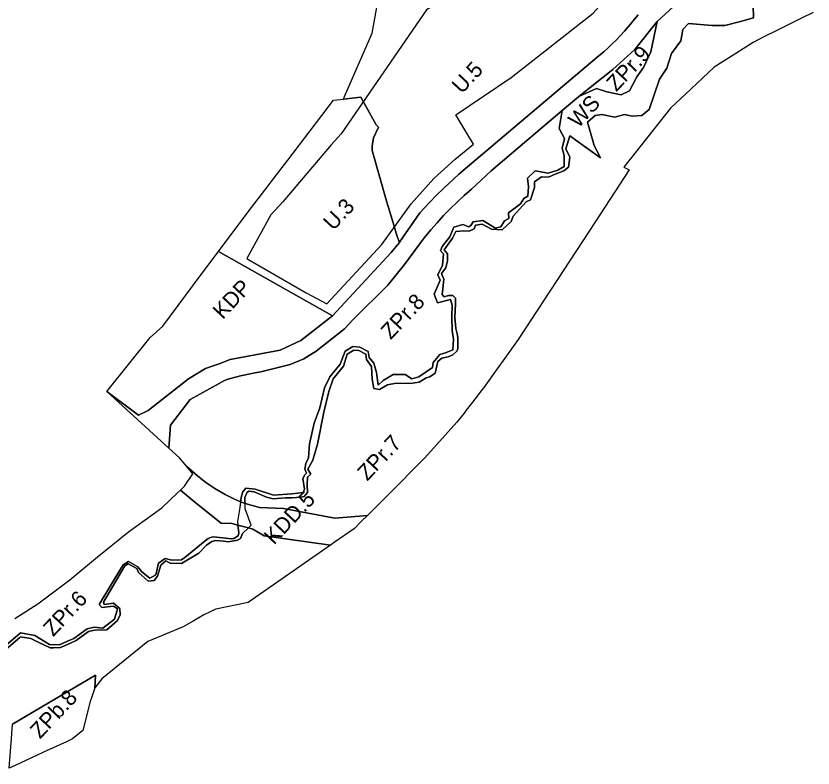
# Model space of a CAD drawing. Extents: x 7425782 to 7428854, y 5550411 to 5553074.
# Drawn here: x 7426859.1 to 7427315.3, y 5551271.3 to 5551702 of the extents above; entities that cross this region are included whole.
import ezdxf

# ---------------------------------------------------------------- set-up
doc = ezdxf.new("R2010")
doc.units = 0
for name, color, linetype in [('LIN_Linie rozgraniczajace WS', 7, 'Continuous'), ('LIN_linie_rozgraniczajace', 7, 'Continuous'), ('LIN_nieprzekraczalna linia zabudowy', 7, 'Continuous'), ('TXT_oznaczenia przeznaczen', 7, 'Continuous')]:
    doc.layers.add(name, color=color, linetype=linetype)

msp = doc.modelspace()

# ---------------------------------------------------------------- linework, layer by layer
at = {"layer": 'LIN_Linie rozgraniczajace WS'}
for points in [[(7426987.63, 5551423.77), (7426987.13, 5551420.51), (7426985.88, 5551412.53), (7426986.15, 5551410.37)], [(7426992.14, 5551408.81), (7426993.77, 5551410.36), (7426990.26, 5551419.81), (7426990.19, 5551422.72)]]:
    msp.add_lwpolyline(points, dxfattribs=at)
at = {"layer": 'LIN_linie_rozgraniczajace'}
for points in [[(7427215.26, 5551702.62), (7427212.2, 5551698.98), (7427211.72, 5551698.4), (7427209.57, 5551695.83), (7427207.36, 5551693.31), (7427205.08, 5551690.85), (7427202.76, 5551688.43), (7427200.38, 5551686.07), (7427197.94, 5551683.76), (7427195.46, 5551681.51), (7427192.92, 5551679.31), (7427112.56, 5551611.38), (7427103.79, 5551603.22), (7427099.74, 5551599.29), (7427095.81, 5551595.24), (7427090.26, 5551589.21), (7427078.65, 5551572.44), (7427078.53, 5551572.29), (7427077.23, 5551575.79), (7427074.41, 5551585.38), (7427071.29, 5551595.45), (7427062.98, 5551625.05), (7427063.01, 5551627.44), (7427063.81, 5551632.16), (7427066.54, 5551638.39), (7427065.17, 5551639.71), (7427056.47, 5551655.47), (7427046.51, 5551654.42), (7427047.03, 5551655.97), (7427062.95, 5551692.14), (7427066.49, 5551712.37)], [(7427240.05, 5551711.78), (7427226.11, 5551698.89), (7427213.3, 5551682.79), (7427200.78, 5551671.27), (7427181.31, 5551655.85), (7427171.71, 5551647.91), (7427131.08, 5551613.29), (7427119.82, 5551602.79), (7427115.67, 5551599.17), (7427111.61, 5551595.44), (7427107.67, 5551591.6), (7427103.83, 5551587.66), (7427100.1, 5551583.6), (7427096.49, 5551579.45), (7427092.99, 5551575.19), (7427089.97, 5551571.31), (7427081.48, 5551559.65), (7427071.96, 5551547.87), (7427052.36, 5551528.36), (7427047.04, 5551522.85), (7427030.93, 5551510.01), (7427023.9, 5551505.66), (7427015.96, 5551502.31), (7427000.07, 5551498.33), (7426995.12, 5551497.42), (7426987.59, 5551495.95), (7426979.81, 5551493.76), (7426977.97, 5551493), (7426975.37, 5551491.43), (7426958.84, 5551482.32), (7426947.59, 5551467.59), (7426946.66, 5551454.53), (7426911.05, 5551487.01), (7426929.18, 5551473.42), (7426934.76, 5551476.14), (7426957.8, 5551494.22), (7426967.61, 5551500.12), (7426972.44, 5551501.86), (7426975.4, 5551502.85), (7426981.69, 5551505.17), (7427010.32, 5551510.52), (7427022.17, 5551516.16), (7427040.25, 5551530.24), (7427073.8, 5551566.57), (7427078.53, 5551572.29), (7427078.65, 5551572.44), (7427090.26, 5551589.21), (7427095.81, 5551595.24), (7427099.74, 5551599.29), (7427103.79, 5551603.22), (7427112.56, 5551611.38), (7427192.92, 5551679.31), (7427195.46, 5551681.51), (7427197.94, 5551683.76), (7427200.38, 5551686.07), (7427202.76, 5551688.43), (7427205.08, 5551690.85), (7427207.36, 5551693.31), (7427209.57, 5551695.83), (7427211.72, 5551698.4), (7427212.2, 5551698.98), (7427215.26, 5551702.62)], [(7427281.08, 5551708.22), (7427281.22, 5551700.92), (7427273.77, 5551698.78), (7427264.87, 5551696.48), (7427257.57, 5551696.47), (7427243.93, 5551697.6), (7427240.78, 5551694.21), (7427239.69, 5551687.75), (7427234.21, 5551680.55), (7427231.68, 5551672.18), (7427227.37, 5551665.82), (7427221.44, 5551648.35), (7427217.28, 5551645.06), (7427211.77, 5551644.6), (7427207.42, 5551645.49), (7427201.92, 5551644.04), (7427194.4, 5551645.55), (7427190.6, 5551645.05), (7427186.22, 5551641.16), (7427190.06, 5551627.77), (7427193.66, 5551620.75), (7427185.56, 5551626.47), (7427176.02, 5551633.45), (7427173.77, 5551625.86), (7427176.01, 5551621.2), (7427175.37, 5551615.37), (7427172.73, 5551613.34), (7427167.75, 5551611.38), (7427163.95, 5551609.64), (7427159.95, 5551609.83), (7427155.91, 5551606.94), (7427155.96, 5551603.75), (7427153.61, 5551596.74), (7427151.1, 5551595.51), (7427143.6, 5551587.42), (7427142.52, 5551584.39), (7427137.34, 5551579.46), (7427131.26, 5551579.9), (7427125.93, 5551582.86), (7427122.07, 5551582.23), (7427121.32, 5551580.06), (7427118.57, 5551578.84), (7427115.4, 5551579.02), (7427110.83, 5551578.55), (7427108.96, 5551574.68), (7427104.25, 5551568.07), (7427106.16, 5551565.69), (7427106.1, 5551561.83), (7427105.19, 5551557.67), (7427102.64, 5551554.49), (7427103.99, 5551551.21), (7427103.49, 5551545.69), (7427102.96, 5551542.49), (7427104.14, 5551541.21), (7427106.67, 5551541.97), (7427109.16, 5551541.89), (7427110.69, 5551540.38), (7427110.74, 5551537.16), (7427110.29, 5551529.39), (7427110.89, 5551523.07), (7427111.63, 5551520.05), (7427111.92, 5551517.82), (7427112.01, 5551511.54), (7427111.58, 5551510.2), (7427109.21, 5551507.86), (7427106.37, 5551506.83), (7427102.75, 5551505.99), (7427100.59, 5551504.15), (7427098.99, 5551497.53), (7427095.92, 5551495.28), (7427093.9, 5551494.73), (7427089.89, 5551492.27), (7427084.88, 5551491.47), (7427076.69, 5551491.8), (7427071.64, 5551490.77), (7427067.13, 5551488), (7427064, 5551488.56), (7427062.89, 5551493.97), (7427062.5, 5551501.26), (7427059.62, 5551505.21), (7427059.32, 5551508.3), (7427055.26, 5551510.5), (7427052.47, 5551510.64), (7427048.64, 5551508.41), (7427046.55, 5551501.45), (7427040.6, 5551494.22), (7427038.22, 5551486.86), (7427035.31, 5551475.07), (7427031.75, 5551456.79), (7427028.92, 5551447.59), (7427026.22, 5551442.49), (7427027.85, 5551439.5), (7427025.86, 5551437.94), (7427025.83, 5551433.52), (7427025.85, 5551429.01), (7427024, 5551426.8), (7427022.12, 5551426.49), (7427017.19, 5551426.09), (7427013.32, 5551426.01), (7427006.26, 5551425.5), (7427002.41, 5551426.44), (7426995.39, 5551429.47), (7426992.31, 5551429.78), (7426991.33, 5551429.27), (7426990.09, 5551426.25), (7426990.14, 5551424.38), (7426990.19, 5551422.72), (7426987.63, 5551423.77), (7426988.14, 5551427.03), (7426988.84, 5551429.54), (7426990.68, 5551431.55), (7426995.97, 5551431.06), (7427006.46, 5551427.54), (7427016.99, 5551428.29), (7427023.37, 5551429.09), (7427024.14, 5551431.01), (7427023.26, 5551437.08), (7427024.37, 5551439.21), (7427025.34, 5551440.2), (7427024.4, 5551442.45), (7427024.99, 5551445.75), (7427026.45, 5551449.03), (7427027.12, 5551456.99), (7427029.76, 5551468.86), (7427033.06, 5551477.52), (7427035.71, 5551489.12), (7427038.81, 5551495.42), (7427044.62, 5551502.67), (7427047.54, 5551510.07), (7427051.95, 5551512.71), (7427055.81, 5551512.24), (7427060.69, 5551509.84), (7427061.28, 5551506.36), (7427063.95, 5551503.12), (7427065.47, 5551497.77), (7427066.34, 5551490.59), (7427069.25, 5551493.31), (7427075, 5551496.66), (7427081.92, 5551496.6), (7427085.65, 5551494.28), (7427089.74, 5551495.24), (7427097.54, 5551500.6), (7427097.94, 5551503.48), (7427101.71, 5551508.22), (7427104.99, 5551509.06), (7427109.21, 5551510.73), (7427109.56, 5551516.93), (7427108.79, 5551521.92), (7427108.56, 5551529.7), (7427108.73, 5551536.46), (7427107.77, 5551539.69), (7427100.39, 5551537.74), (7427098.38, 5551542.62), (7427101.89, 5551550.69), (7427100.45, 5551553.73), (7427103.12, 5551559.27), (7427103.81, 5551565.82), (7427102.05, 5551567.56), (7427102.96, 5551569.97), (7427107.48, 5551575.45), (7427109.73, 5551581.06), (7427114.81, 5551582.57), (7427118.34, 5551581.16), (7427119.5, 5551581.99), (7427120.8, 5551584.18), (7427126.38, 5551584.81), (7427133.57, 5551580.45), (7427136.57, 5551581.19), (7427138.66, 5551584.76), (7427141.24, 5551585.99), (7427141.05, 5551589.29), (7427147.79, 5551594.5), (7427149.85, 5551597.56), (7427152.01, 5551598.74), (7427152.43, 5551604.43), (7427151.78, 5551609.06), (7427156.21, 5551613.35), (7427163.75, 5551612.04), (7427169.29, 5551613.77), (7427172.83, 5551615.88), (7427172.84, 5551622.01), (7427171.77, 5551626.27), (7427173.05, 5551631.91), (7427170.07, 5551637.59), (7427171.71, 5551647.91), (7427181.31, 5551655.85), (7427191.28, 5551660.53), (7427197.34, 5551658.49), (7427205.41, 5551656.8), (7427210.2, 5551659.15), (7427214.35, 5551667.11), (7427218.31, 5551672.58), (7427222.37, 5551681.5), (7427226.11, 5551698.89), (7427240.05, 5551711.78)], [(7427315.31, 5551703.95), (7427308.73, 5551700.68), (7427294.23, 5551693.48), (7427287.53, 5551690.16), (7427280.94, 5551686.89), (7427271.15, 5551680.59), (7427258.71, 5551672.59), (7427245.44, 5551660.18), (7427233.77, 5551649.26), (7427207.05, 5551615.38), (7427207.05, 5551615.38), (7427209.69, 5551614.03), (7427210.14, 5551613.8), (7427190.78, 5551584.27), (7427146.54, 5551516.77), (7427126.82, 5551489.17), (7427126.66, 5551488.96), (7427123.99, 5551485.52), (7427122.44, 5551483.51), (7427116.85, 5551476.28), (7427115.52, 5551474.56), (7427111.46, 5551469.31), (7427093.09, 5551448.86), (7427071.71, 5551427.46), (7427060.25, 5551415.99), (7427060.25, 5551415.99), (7427041.59, 5551414.41), (7427012.28, 5551419.87), (7426998.38, 5551420.46), (7426990.19, 5551422.72), (7426990.14, 5551424.38), (7426990.09, 5551426.25), (7426991.33, 5551429.27), (7426992.31, 5551429.78), (7426995.39, 5551429.47), (7427002.41, 5551426.44), (7427006.26, 5551425.5), (7427013.32, 5551426.01), (7427017.19, 5551426.09), (7427022.12, 5551426.49), (7427024, 5551426.8), (7427025.85, 5551429.01), (7427025.83, 5551433.52), (7427025.86, 5551437.94), (7427027.85, 5551439.5), (7427026.22, 5551442.49), (7427028.92, 5551447.59), (7427031.75, 5551456.79), (7427035.31, 5551475.07), (7427038.22, 5551486.86), (7427040.6, 5551494.22), (7427046.55, 5551501.45), (7427048.64, 5551508.41), (7427052.47, 5551510.64), (7427055.26, 5551510.5), (7427059.32, 5551508.3), (7427059.62, 5551505.21), (7427062.5, 5551501.26), (7427062.89, 5551493.97), (7427064, 5551488.56), (7427067.13, 5551488), (7427071.64, 5551490.77), (7427076.69, 5551491.8), (7427084.88, 5551491.47), (7427089.89, 5551492.27), (7427093.9, 5551494.73), (7427095.92, 5551495.28), (7427098.99, 5551497.53), (7427100.59, 5551504.15), (7427102.75, 5551505.99), (7427106.37, 5551506.83), (7427109.21, 5551507.86), (7427111.58, 5551510.2), (7427112.01, 5551511.54), (7427111.92, 5551517.82), (7427111.63, 5551520.05), (7427110.89, 5551523.07), (7427110.29, 5551529.39), (7427110.74, 5551537.16), (7427110.69, 5551540.38), (7427109.16, 5551541.89), (7427106.67, 5551541.97), (7427104.14, 5551541.21), (7427102.96, 5551542.49), (7427103.49, 5551545.69), (7427103.99, 5551551.21), (7427102.64, 5551554.49), (7427105.19, 5551557.67), (7427106.1, 5551561.83), (7427106.16, 5551565.69), (7427104.25, 5551568.07), (7427108.96, 5551574.68), (7427110.83, 5551578.55), (7427115.4, 5551579.02), (7427118.57, 5551578.84), (7427121.32, 5551580.06), (7427122.07, 5551582.23), (7427125.93, 5551582.86), (7427131.26, 5551579.9), (7427137.34, 5551579.46), (7427142.52, 5551584.39), (7427143.6, 5551587.42), (7427151.1, 5551595.51), (7427153.61, 5551596.74), (7427155.96, 5551603.75), (7427155.91, 5551606.94), (7427159.95, 5551609.83), (7427163.95, 5551609.64), (7427167.75, 5551611.38), (7427172.73, 5551613.34), (7427175.37, 5551615.37), (7427176.01, 5551621.2), (7427173.77, 5551625.86), (7427176.02, 5551633.45), (7427185.56, 5551626.47), (7427193.66, 5551620.75), (7427190.06, 5551627.77), (7427186.22, 5551641.16), (7427190.6, 5551645.05), (7427194.4, 5551645.55), (7427201.92, 5551644.04), (7427207.42, 5551645.49), (7427211.77, 5551644.6), (7427217.28, 5551645.06), (7427221.44, 5551648.35), (7427227.37, 5551665.82), (7427231.68, 5551672.18), (7427234.21, 5551680.55), (7427239.69, 5551687.75), (7427240.78, 5551694.21), (7427243.93, 5551697.6), (7427257.57, 5551696.47), (7427264.87, 5551696.48), (7427273.77, 5551698.78), (7427281.22, 5551700.92), (7427281.08, 5551708.22)], [(7426858.52, 5551356.89), (7426871.59, 5551365.28), (7426889.82, 5551378.99), (7426904.52, 5551391.21), (7426923.5, 5551406.59), (7426942.59, 5551420.23), (7426951.55, 5551428.85), (7426953.18, 5551430.37), (7426961.54, 5551423.51), (7426976.56, 5551411.51), (7426982.65, 5551411.28), (7426986.15, 5551410.37), (7426986.71, 5551405.97), (7426986.31, 5551404.35), (7426983.7, 5551402.69), (7426982.44, 5551402.57), (7426972.12, 5551403.64), (7426971.06, 5551403.45), (7426969.11, 5551402.82), (7426967.43, 5551401.37), (7426955.66, 5551391.86), (7426953.9, 5551390.58), (7426948.21, 5551390.29), (7426944.55, 5551391.37), (7426940.74, 5551388.66), (7426939.16, 5551381.96), (7426935.62, 5551379.99), (7426931.04, 5551383.72), (7426928.85, 5551386.59), (7426923.4, 5551389.48), (7426920.44, 5551387.65), (7426919.56, 5551386.16), (7426906.64, 5551364.96), (7426908.28, 5551363.28), (7426914.83, 5551364.05), (7426917.21, 5551362.39), (7426915.54, 5551356.48), (7426908.72, 5551351.42), (7426903.8, 5551351.98), (7426899.87, 5551351.08), (7426892.17, 5551345.44), (7426883.71, 5551341.77), (7426878.32, 5551341.99), (7426869.91, 5551347.17), (7426861.62, 5551348.67), (7426839.69, 5551329.93)], [(7426839.69, 5551329.93), (7426861.62, 5551348.67), (7426869.91, 5551347.17), (7426878.32, 5551341.99), (7426883.71, 5551341.77), (7426892.17, 5551345.44), (7426899.87, 5551351.08), (7426903.8, 5551351.98), (7426908.72, 5551351.42), (7426915.54, 5551356.48), (7426917.21, 5551362.39), (7426914.83, 5551364.05), (7426908.28, 5551363.28), (7426906.64, 5551364.96), (7426919.56, 5551386.16), (7426920.44, 5551387.65), (7426923.4, 5551389.48), (7426928.85, 5551386.59), (7426931.04, 5551383.72), (7426935.62, 5551379.99), (7426939.16, 5551381.96), (7426940.74, 5551388.66), (7426944.55, 5551391.37), (7426948.21, 5551390.29), (7426953.9, 5551390.58), (7426955.66, 5551391.86), (7426967.43, 5551401.37), (7426969.11, 5551402.82), (7426971.06, 5551403.45), (7426972.12, 5551403.64), (7426982.44, 5551402.57), (7426983.7, 5551402.69), (7426986.31, 5551404.35), (7426986.71, 5551405.97), (7426986.15, 5551410.37), (7426992.14, 5551408.81), (7426988.78, 5551405.6), (7426987.6, 5551402.71), (7426985.81, 5551401.7), (7426980.8, 5551400.93), (7426977.82, 5551401.14), (7426973.47, 5551401.51), (7426971.21, 5551401.11), (7426968.2, 5551398.89), (7426963.66, 5551394.3), (7426953.77, 5551388.36), (7426947.42, 5551388.58), (7426944.89, 5551389.9), (7426941.93, 5551387.49), (7426940.18, 5551381.08), (7426938.16, 5551378.6), (7426934.83, 5551378.32), (7426929.23, 5551383.31), (7426928.25, 5551385.5), (7426923.24, 5551388.26), (7426921.31, 5551387.15), (7426909.12, 5551366.22), (7426909.49, 5551364.86), (7426914.86, 5551365.74), (7426918.47, 5551362.67), (7426918.79, 5551358.97), (7426917.19, 5551355.87), (7426911.12, 5551350.42), (7426904.07, 5551350.24), (7426900.5, 5551349.44), (7426893.54, 5551344.38), (7426890.23, 5551342.85), (7426884.59, 5551340.26), (7426880.65, 5551340.14), (7426878.59, 5551340.08), (7426871.69, 5551343.44), (7426867.57, 5551345.45), (7426861.7, 5551346.44), (7426861.25, 5551346.13), (7426841.49, 5551329.22)], [(7426841.49, 5551329.22), (7426861.25, 5551346.13), (7426861.7, 5551346.44), (7426867.57, 5551345.45), (7426871.69, 5551343.44), (7426878.59, 5551340.08), (7426880.65, 5551340.14), (7426884.59, 5551340.26), (7426890.23, 5551342.85), (7426893.54, 5551344.38), (7426900.5, 5551349.44), (7426904.07, 5551350.24), (7426911.12, 5551350.42), (7426917.19, 5551355.87), (7426918.79, 5551358.97), (7426918.47, 5551362.67), (7426914.86, 5551365.74), (7426909.49, 5551364.86), (7426909.12, 5551366.22), (7426921.31, 5551387.15), (7426923.24, 5551388.26), (7426928.25, 5551385.5), (7426929.23, 5551383.31), (7426934.83, 5551378.32), (7426938.16, 5551378.6), (7426940.18, 5551381.08), (7426941.93, 5551387.49), (7426944.89, 5551389.9), (7426947.42, 5551388.58), (7426953.77, 5551388.36), (7426963.66, 5551394.3), (7426968.2, 5551398.89), (7426971.21, 5551401.11), (7426973.47, 5551401.51), (7426977.82, 5551401.14), (7426980.8, 5551400.93), (7426985.81, 5551401.7), (7426987.6, 5551402.71), (7426988.78, 5551405.6), (7426992.14, 5551408.81), (7426994.66, 5551408.16), (7427001.19, 5551404.33), (7427039.16, 5551398.99), (7427039.16, 5551398.99), (7426992.01, 5551366.07), (7426973.57, 5551362.21), (7426969.94, 5551360.49), (7426966.65, 5551358.94), (7426960.47, 5551355.41), (7426954.82, 5551352.18), (7426934.6, 5551343.67), (7426934.6, 5551343.67), (7426908.28, 5551322.32), (7426904.25, 5551317.27), (7426904.68, 5551324.5), (7426857.13, 5551296.4)]]:
    msp.add_lwpolyline(points, dxfattribs=at)
for points in [[(7427181.31, 5551655.85), (7427200.78, 5551671.27), (7427213.3, 5551682.79), (7427226.11, 5551698.89), (7427222.37, 5551681.5), (7427218.31, 5551672.58), (7427214.35, 5551667.11), (7427210.2, 5551659.15), (7427205.41, 5551656.8), (7427197.34, 5551658.49), (7427191.28, 5551660.53)], [(7427078.53, 5551572.29), (7427073.8, 5551566.57), (7427040.25, 5551530.24), (7426974.95, 5551567.07), (7426992, 5551589.77), (7427003.48, 5551604.79), (7427006.34, 5551608.53), (7427014.69, 5551619.47), (7427040.87, 5551653.76), (7427046.51, 5551654.42), (7427056.47, 5551655.47), (7427065.17, 5551639.71), (7427066.54, 5551638.39), (7427063.81, 5551632.16), (7427063.01, 5551627.44), (7427062.98, 5551625.05), (7427071.29, 5551595.45), (7427074.41, 5551585.38), (7427077.23, 5551575.79)], [(7426987.63, 5551423.77), (7426983.71, 5551425.45), (7426978.79, 5551427.92), (7426972.96, 5551431.32), (7426967.76, 5551434.86), (7426962.89, 5551438.66), (7426956.8, 5551444.07), (7426952.76, 5551448.96), (7426946.66, 5551454.53), (7426947.59, 5551467.59), (7426958.84, 5551482.32), (7426975.37, 5551491.43), (7426977.97, 5551493), (7426979.81, 5551493.76), (7426987.59, 5551495.95), (7426995.12, 5551497.42), (7427000.07, 5551498.33), (7427015.96, 5551502.31), (7427023.9, 5551505.66), (7427030.93, 5551510.01), (7427047.04, 5551522.85), (7427052.36, 5551528.36), (7427071.96, 5551547.87), (7427081.48, 5551559.65), (7427089.97, 5551571.31), (7427092.99, 5551575.19), (7427096.49, 5551579.45), (7427100.1, 5551583.6), (7427103.83, 5551587.66), (7427107.67, 5551591.6), (7427111.61, 5551595.44), (7427115.67, 5551599.17), (7427119.82, 5551602.79), (7427131.08, 5551613.29), (7427171.71, 5551647.91), (7427170.07, 5551637.59), (7427173.05, 5551631.91), (7427171.77, 5551626.27), (7427172.84, 5551622.01), (7427172.83, 5551615.88), (7427169.29, 5551613.77), (7427163.75, 5551612.04), (7427156.21, 5551613.35), (7427151.78, 5551609.06), (7427152.43, 5551604.43), (7427152.01, 5551598.74), (7427149.85, 5551597.56), (7427147.79, 5551594.5), (7427141.05, 5551589.29), (7427141.24, 5551585.99), (7427138.66, 5551584.76), (7427136.57, 5551581.19), (7427133.57, 5551580.45), (7427126.38, 5551584.81), (7427120.8, 5551584.18), (7427119.5, 5551581.99), (7427118.34, 5551581.16), (7427114.81, 5551582.57), (7427109.73, 5551581.06), (7427107.48, 5551575.45), (7427102.96, 5551569.97), (7427102.05, 5551567.56), (7427103.81, 5551565.82), (7427103.12, 5551559.27), (7427100.45, 5551553.73), (7427101.89, 5551550.69), (7427098.38, 5551542.62), (7427100.39, 5551537.74), (7427107.77, 5551539.69), (7427108.73, 5551536.46), (7427108.56, 5551529.7), (7427108.79, 5551521.92), (7427109.56, 5551516.93), (7427109.21, 5551510.73), (7427104.99, 5551509.06), (7427101.71, 5551508.22), (7427097.94, 5551503.48), (7427097.54, 5551500.6), (7427089.74, 5551495.24), (7427085.65, 5551494.28), (7427081.92, 5551496.6), (7427075, 5551496.66), (7427069.25, 5551493.31), (7427066.34, 5551490.59), (7427065.47, 5551497.77), (7427063.95, 5551503.12), (7427061.28, 5551506.36), (7427060.69, 5551509.84), (7427055.81, 5551512.24), (7427051.95, 5551512.71), (7427047.54, 5551510.07), (7427044.62, 5551502.67), (7427038.81, 5551495.42), (7427035.71, 5551489.12), (7427033.06, 5551477.52), (7427029.76, 5551468.86), (7427027.12, 5551456.99), (7427026.45, 5551449.03), (7427024.99, 5551445.75), (7427024.4, 5551442.45), (7427025.34, 5551440.2), (7427024.37, 5551439.21), (7427023.26, 5551437.08), (7427024.14, 5551431.01), (7427023.37, 5551429.09), (7427016.99, 5551428.29), (7427006.46, 5551427.54), (7426995.97, 5551431.06), (7426990.68, 5551431.55), (7426988.84, 5551429.54), (7426988.14, 5551427.03)], [(7427040.25, 5551530.24), (7427022.17, 5551516.16), (7427010.32, 5551510.52), (7426981.69, 5551505.17), (7426975.4, 5551502.85), (7426972.44, 5551501.86), (7426967.61, 5551500.12), (7426957.8, 5551494.22), (7426934.76, 5551476.14), (7426929.18, 5551473.42), (7426911.05, 5551487.01), (7426935.85, 5551517.88), (7426943.05, 5551524.29), (7426965.12, 5551554), (7426974.95, 5551567.07)], [(7427012.28, 5551419.87), (7427041.59, 5551414.41), (7427060.25, 5551415.99), (7427060.25, 5551415.99), (7427056.88, 5551412.61), (7427052.76, 5551408.48), (7427041.25, 5551400.45), (7427039.16, 5551398.99), (7427001.19, 5551404.33), (7426994.66, 5551408.16), (7426992.14, 5551408.81), (7426986.15, 5551410.37), (7426982.65, 5551411.28), (7426976.56, 5551411.51), (7426961.54, 5551423.51), (7426953.18, 5551430.37), (7426955.61, 5551432.63), (7426960.37, 5551439.75), (7426956.8, 5551444.07), (7426962.89, 5551438.66), (7426967.76, 5551434.86), (7426972.96, 5551431.32), (7426978.79, 5551427.92), (7426983.71, 5551425.45), (7426987.63, 5551423.77), (7426990.19, 5551422.72), (7426998.38, 5551420.46)], [(7426861.45, 5551274.13), (7426855.24, 5551271.27), (7426856.53, 5551288.18), (7426857.13, 5551296.4), (7426904.68, 5551324.5), (7426904.25, 5551317.27), (7426902.48, 5551312.15), (7426901.55, 5551309.45), (7426897.29, 5551292.77), (7426891.44, 5551287.93), (7426887.61, 5551286.17), (7426886.32, 5551285.58), (7426878.27, 5551281.87), (7426877.37, 5551281.46), (7426877.37, 5551281.46), (7426868.27, 5551277.27)]]:
    msp.add_lwpolyline(points, close=True, dxfattribs=at)
at = {"layer": 'LIN_nieprzekraczalna linia zabudowy'}
for points in [[(7427224.2, 5551783.28), (7427162.34, 5551746.19), (7427094, 5551705.47), (7427045.17, 5551634.42), (7427039.46, 5551628.26), (7427011.8, 5551595.49), (7427005.05, 5551588.21), (7426991.22, 5551563.06), (7426993.16, 5551561.88)], [(7426993.16, 5551561.88), (7427025.17, 5551543.48), (7427037.06, 5551537.1), (7427068.53, 5551571.17), (7427085.36, 5551594.5), (7427098.17, 5551608.93), (7427110.43, 5551620.01), (7427120.9, 5551628.57), (7427117.16, 5551634.81), (7427110.82, 5551645.31), (7427142.46, 5551666.72), (7427189.47, 5551703.52), (7427214.29, 5551731.49), (7427242.1, 5551755.43)]]:
    msp.add_lwpolyline(points, dxfattribs=at)

# ---------------------------------------------------------------- texts
at = {"layer": 'TXT_oznaczenia przeznaczen'}
for s, p in [('ZPr.9', (7427202.71, 5551658.26)), ('U.5', (7427114.23, 5551656.97)), ('WS', (7427180.84, 5551637.35)), ('U.3', (7427040.69, 5551578.64)), ('KDP', (7426977.4, 5551527.82)), ('ZPr.8', (7427073.58, 5551516.26)), ('ZPr.7', (7427060.16, 5551435.27)), ('KDD.5', (7427006.72, 5551398.71)), ('ZPr.6', (7426880.38, 5551346.13)), ('ZPb.8', (7426872.85, 5551287.58))]:
    msp.add_text(s, height=9, rotation=46.7736, dxfattribs=at).set_placement(p)

doc.saveas('drawing.dxf')
